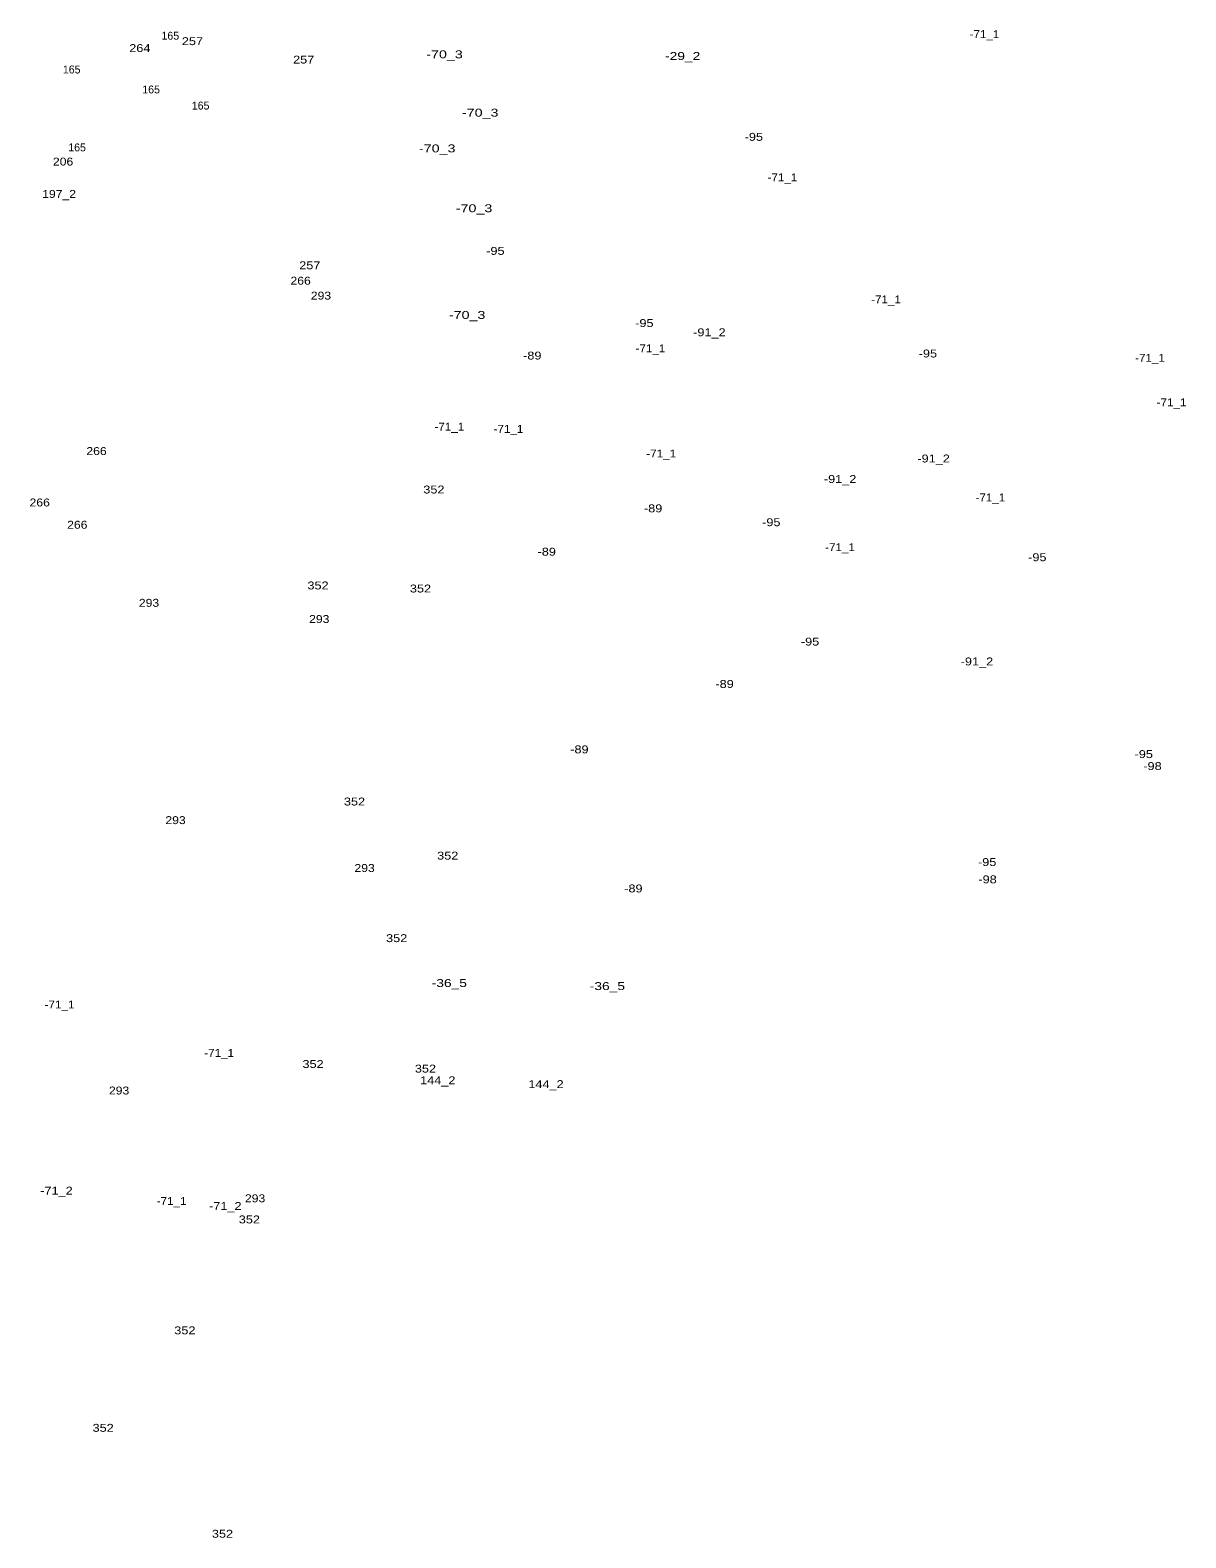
# Model space of a CAD drawing. Extents: x -658110 to -655750, y -1000429 to -997657.
# Drawn here: x -656917 to -656333, y -999881 to -999119 of the extents above; entities that cross this region are included whole.
import ezdxf
from ezdxf.enums import TextEntityAlignment as Align

# ---------------------------------------------------------------- set-up
doc = ezdxf.new("R2010")
doc.units = 0
doc.header["$LTSCALE"] = 1.6
doc.layers.add('24', color=7, linetype='Continuous')

msp = doc.modelspace()

# ---------------------------------------------------------------- texts
at = {"layer": '24'}
for p in [(-656845.88, -999123.45), (-656895.711, -999140.51), (-656855.581, -999150.6), (-656830.571, -999158.74), (-656892.99, -999179.88)]:
    msp.add_text('165', height=4, dxfattribs=at).set_placement(p, align=Align.CENTER)
for s, width, p in [('-71_1', 1.1, (-656434.541, -999122.63)), ('264', 1.2, (-656861.28, -999129.71)), ('257', 1.2, (-656834.72, -999126.2)), ('257', 1.2, (-656778.5, -999135.51)), ('-70_3', 1.35, (-656707.35, -999132.85)), ('-29_2', 1.3, (-656587.02, -999133.71)), ('-70_3', 1.35, (-656689.32, -999162.33)), ('-95', 1.2, (-656551.06, -999174.55)), ('-70_3', 1.35, (-656711.03, -999180.38)), ('206', 1.15, (-656900.071, -999187.04)), ('-71_1', 1.1, (-656536.601, -999195.02)), ('197_2', 1.15, (-656902.081, -999203.41)), ('-70_3', 1.35, (-656692.42, -999210.64)), ('-95', 1.2, (-656681.64, -999232.17)), ('257', 1.2, (-656775.4, -999239.46)), ('266', 1.15, (-656780.05, -999247.23)), ('293', 1.15, (-656769.77, -999254.79)), ('-71_1', 1.1, (-656484.26, -999256.69)), ('-70_3', 1.35, (-656695.91, -999264.55)), ('-95', 1.2, (-656606.37, -999268.66)), ('-91_2', 1.2, (-656573.51, -999273.32)), ('-71_1', 1.1, (-656603.291, -999281.44)), ('-95', 1.2, (-656463.12, -999284.03)), ('-89', 1.2, (-656663, -999285.08)), ('-71_1', 1.1, (-656350.88, -999286.22)), ('-71_1', 1.1, (-656340.02, -999308.72)), ('-71_1', 1.1, (-656704.88, -999320.97)), ('-71_1', 1.1, (-656675.03, -999322.14)), ('266', 1.15, (-656883.18, -999333.34)), ('-71_1', 1.1, (-656597.861, -999334.58)), ('-91_2', 1.2, (-656460.231, -999337.09)), ('352', 1.2, (-656712.709, -999352.77)), ('-91_2', 1.2, (-656507.461, -999347.46)), ('266', 1.15, (-656911.88, -999359.32)), ('-71_1', 1.1, (-656431.53, -999356.76)), ('-89', 1.2, (-656601.94, -999362.29)), ('266', 1.15, (-656892.88, -999370.57)), ('-95', 1.2, (-656542.23, -999369.31)), ('-71_1', 1.1, (-656507.52, -999381.9)), ('-89', 1.2, (-656655.7, -999384.19)), ('-95', 1.2, (-656407.82, -999386.98)), ('352', 1.2, (-656771.25, -999401.25)), ('352', 1.2, (-656719.49, -999402.8)), ('293', 1.15, (-656856.64, -999410.02)), ('293', 1.15, (-656770.64, -999418.23)), ('-95', 1.2, (-656522.65, -999429.62)), ('-91_2', 1.2, (-656438.341, -999439.65)), ('-89', 1.2, (-656565.84, -999451.03)), ('-89', 1.2, (-656639.19, -999484.08)), ('-95', 1.2, (-656354.06, -999486.48)), ('-98', 1.2, (-656349.64, -999492.53)), ('352', 1.2, (-656752.829, -999510.44)), ('293', 1.15, (-656843.24, -999519.84)), ('293', 1.15, (-656747.73, -999544.05)), ('352', 1.2, (-656705.72, -999537.78)), ('-95', 1.2, (-656433.17, -999541.03)), ('-98', 1.2, (-656432.97, -999549.77)), ('-89', 1.2, (-656611.92, -999554.37)), ('352', 1.2, (-656731.52, -999579.48)), ('-36_5', 1.3, (-656704.92, -999602.16)), ('-36_5', 1.3, (-656625.05, -999603.71)), ('-71_1', 1.1, (-656901.861, -999613.02)), ('-71_1', 1.1, (-656821.211, -999637.46)), ('352', 1.2, (-656773.77, -999643.09)), ('352', 1.2, (-656716.97, -999645.41)), ('293', 1.15, (-656871.77, -999656.47)), ('144_2', 1.2, (-656710.75, -999651.32)), ('144_2', 1.2, (-656656.071, -999653.26)), ('-71_2', 1.2, (-656903.41, -999707.08)), ('293', 1.15, (-656803.05, -999710.95)), ('-71_1', 1.1, (-656845.25, -999712.32)), ('-71_2', 1.2, (-656818.11, -999714.84)), ('352', 1.2, (-656805.949, -999721.63)), ('352', 1.2, (-656838.53, -999777.68)), ('352', 1.2, (-656879.819, -999826.94)), ('352', 1.2, (-656819.53, -999880.47))]:
    msp.add_text(s, height=4, dxfattribs=dict(at, width=width)).set_placement(p, align=Align.CENTER)

doc.saveas('drawing.dxf')
